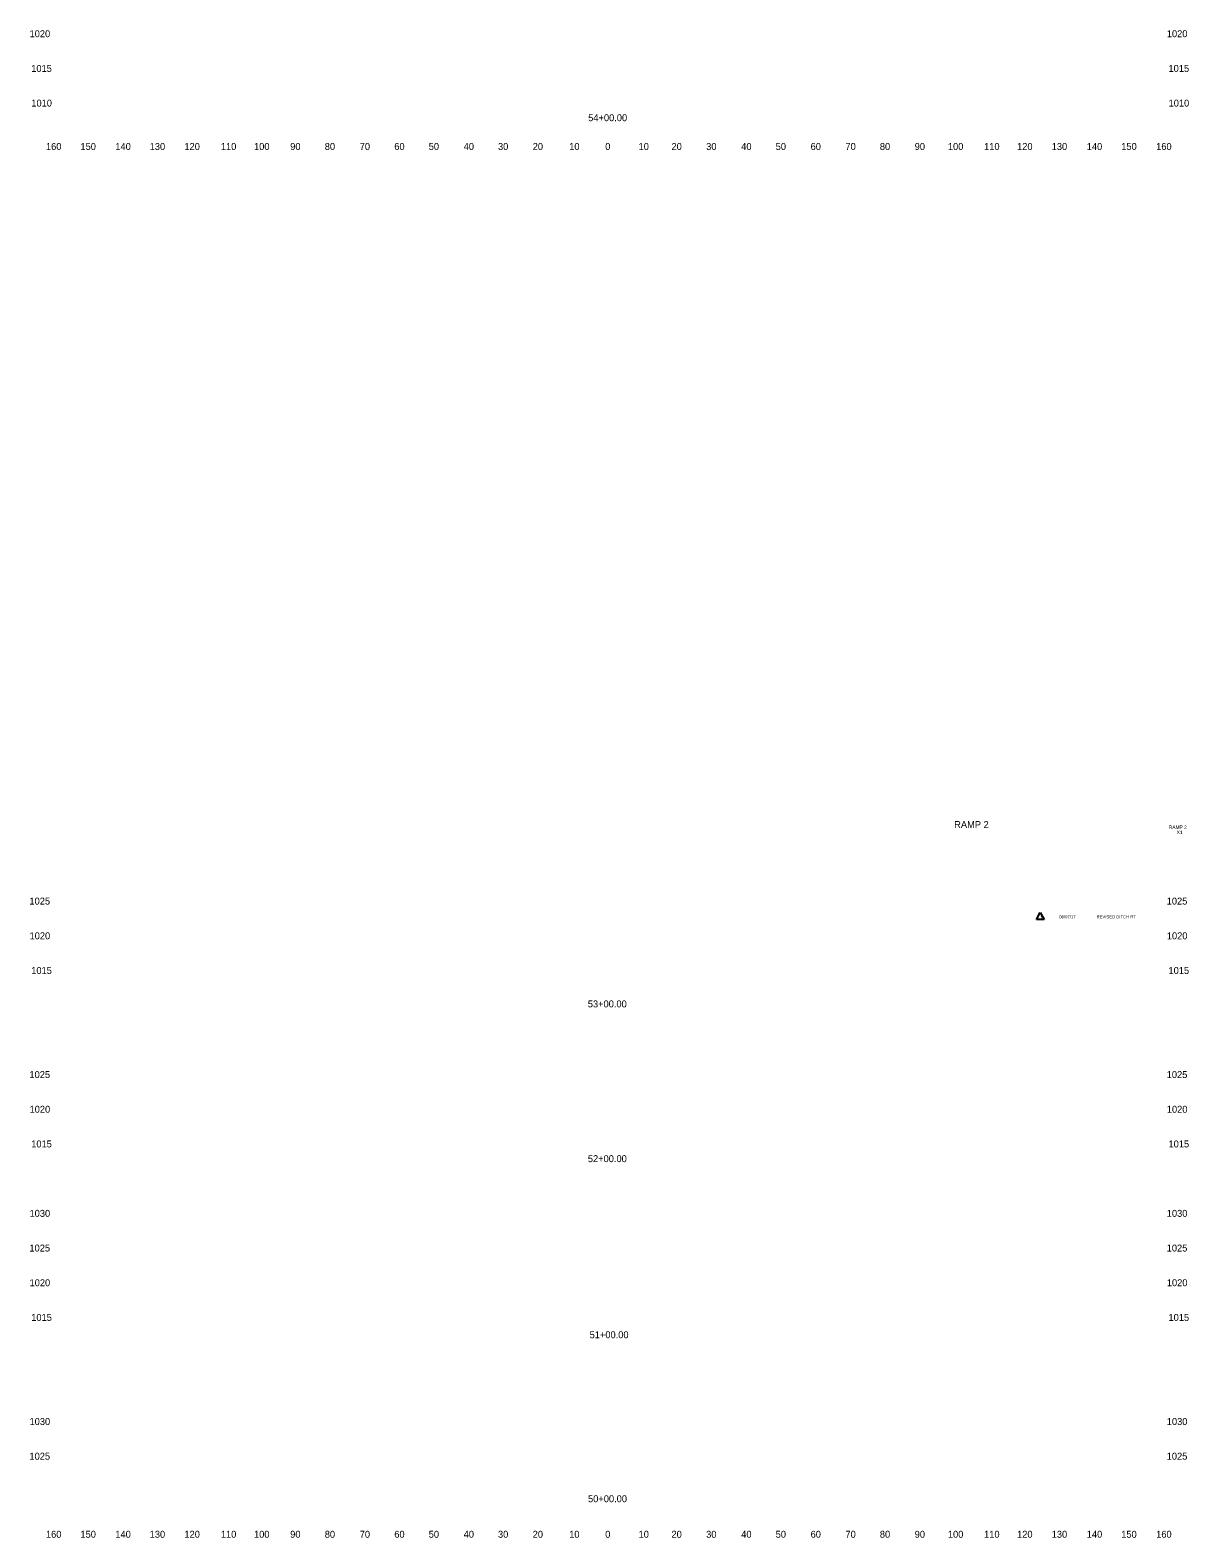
# Model space of a CAD drawing. Extents: x 4994 to 5328, y 4997 to 8804.
# Drawn here: x 4993.5 to 5327.5, y 4997.5 to 5432 of the extents above; entities that cross this region are included whole.
import ezdxf

# ---------------------------------------------------------------- set-up
doc = ezdxf.new("R2010")
doc.units = 0
for name, color, linetype in [('RD_SHT_ID', 7, 'Continuous'), ('RD_SHT_TX', 7, 'Continuous'), ('RD_XS_TX_Offset', 7, 'Continuous'), ('RD_XS_TX_Station', 7, 'Continuous')]:
    doc.layers.add(name, color=color, linetype=linetype)

msp = doc.modelspace()

# ---------------------------------------------------------------- linework, layer by layer
at = {"layer": 'RD_SHT_ID'}
for p, q in [((5283.57, 5175.73), (5284.71, 5177.76)), ((5285.85, 5175.73), (5283.57, 5175.73)), ((5284.71, 5177.76), (5285.85, 5175.73))]:
    msp.add_line(p, q, dxfattribs=at)

# ---------------------------------------------------------------- texts
for s, height, p in [('RAMP 2', 2, (5259.89, 5202.06)), ('RAMP 2', 1, (5321.78, 5201.8)), ('X1', 1, (5324.02, 5200.3))]:
    msp.add_text(s, height=height, dxfattribs=at).set_placement(p)
at = {"layer": 'RD_SHT_TX'}
for s, p in [('1', (5284.6, 5175.97)), ('06/07/17', (5290.15, 5176.02)), ('REVISED DITCH RT', (5300.92, 5176.02))]:
    msp.add_text(s, height=0.88, dxfattribs=at).set_placement(p)
at = {"layer": 'RD_XS_TX_Offset'}
for s, p in [('1020', (4993.37, 5430)), ('1020', (5321.17, 5430)), ('1015', (4993.85, 5420)), ('1015', (5321.65, 5420)), ('1010', (4993.88, 5410)), ('1010', (5321.68, 5410)), ('160', (4998.1, 5397.5)), ('150', (5008.04, 5397.5)), ('140', (5018.1, 5397.5)), ('130', (5027.99, 5397.5)), ('120', (5038.01, 5397.5)), ('110', (5048.51, 5397.5)), ('100', (5058.07, 5397.5)), ('90', (5068.5, 5397.5)), ('80', (5078.46, 5397.5)), ('70', (5088.54, 5397.5)), ('60', (5098.5, 5397.5)), ('50', (5108.43, 5397.5)), ('40', (5118.5, 5397.5)), ('30', (5128.39, 5397.5)), ('20', (5138.4, 5397.5)), ('10', (5148.91, 5397.5)), ('0', (5159.3, 5397.5)), ('0', (5159.3, 5397.5)), ('10', (5168.91, 5397.5)), ('20', (5178.4, 5397.5)), ('30', (5188.39, 5397.5)), ('40', (5198.5, 5397.5)), ('50', (5208.43, 5397.5)), ('60', (5218.5, 5397.5)), ('70', (5228.54, 5397.5)), ('80', (5238.46, 5397.5)), ('90', (5248.5, 5397.5)), ('100', (5258.07, 5397.5)), ('110', (5268.51, 5397.5)), ('120', (5278.01, 5397.5)), ('130', (5287.99, 5397.5)), ('140', (5298.1, 5397.5)), ('150', (5308.04, 5397.5)), ('160', (5318.1, 5397.5)), ('1025', (4993.34, 5180)), ('1025', (5321.14, 5180)), ('1020', (4993.37, 5170)), ('1020', (5321.17, 5170)), ('1015', (4993.85, 5160)), ('1015', (5321.65, 5160)), ('1025', (4993.34, 5130)), ('1025', (5321.14, 5130)), ('1020', (4993.37, 5120)), ('1020', (5321.17, 5120)), ('1015', (4993.85, 5110)), ('1015', (5321.65, 5110)), ('1030', (4993.36, 5090)), ('1030', (5321.16, 5090)), ('1025', (4993.34, 5080)), ('1025', (5321.14, 5080)), ('1020', (4993.37, 5070)), ('1020', (5321.17, 5070)), ('1015', (4993.85, 5060)), ('1015', (5321.65, 5060)), ('1030', (4993.36, 5030)), ('1030', (5321.16, 5030)), ('1025', (4993.34, 5020)), ('1025', (5321.14, 5020)), ('160', (4998.1, 4997.5)), ('150', (5008.04, 4997.5)), ('140', (5018.1, 4997.5)), ('130', (5027.99, 4997.5)), ('120', (5038.01, 4997.5)), ('110', (5048.51, 4997.5)), ('100', (5058.07, 4997.5)), ('90', (5068.5, 4997.5)), ('80', (5078.46, 4997.5)), ('70', (5088.54, 4997.5)), ('60', (5098.5, 4997.5)), ('50', (5108.43, 4997.5)), ('40', (5118.5, 4997.5)), ('30', (5128.39, 4997.5)), ('20', (5138.4, 4997.5)), ('10', (5148.91, 4997.5)), ('0', (5159.3, 4997.5)), ('0', (5159.3, 4997.5)), ('10', (5168.91, 4997.5)), ('20', (5178.4, 4997.5)), ('30', (5188.39, 4997.5)), ('40', (5198.5, 4997.5)), ('50', (5208.43, 4997.5)), ('60', (5218.5, 4997.5)), ('70', (5228.54, 4997.5)), ('80', (5238.46, 4997.5)), ('90', (5248.5, 4997.5)), ('100', (5258.07, 4997.5)), ('110', (5268.51, 4997.5)), ('120', (5278.01, 4997.5)), ('130', (5287.99, 4997.5)), ('140', (5298.1, 4997.5)), ('150', (5308.04, 4997.5)), ('160', (5318.1, 4997.5))]:
    msp.add_text(s, height=2, dxfattribs=at).set_placement(p)
at = {"layer": 'RD_XS_TX_Station'}
for s, p in [('54+00.00', (5154.39, 5405.79)), ('53+00.00', (5154.28, 5150.37)), ('52+00.00', (5154.29, 5105.76)), ('51+00.00', (5154.8, 5055.01)), ('50+00.00', (5154.35, 5007.74))]:
    msp.add_text(s, height=2, dxfattribs=at).set_placement(p)

doc.saveas('drawing.dxf')
